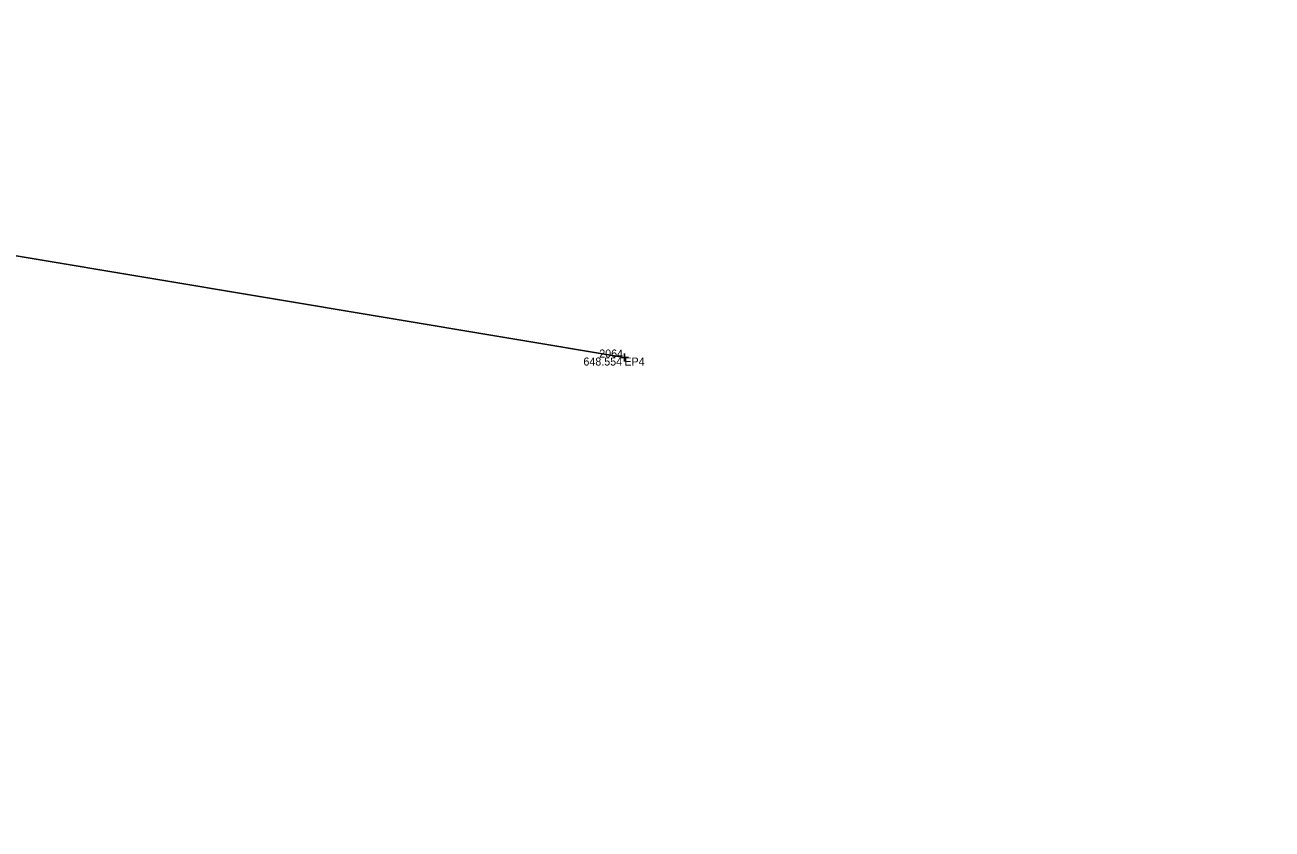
# Model space of a CAD drawing. Extents: x 2197382 to 2204062, y 634117 to 636522.
# Drawn here: x 2202771.2 to 2202927, y 635131.4 to 635231.8 of the extents above; entities that cross this region are included whole.
import ezdxf

# ---------------------------------------------------------------- set-up
doc = ezdxf.new("R2010")
doc.units = 0
for name, color, linetype in [('_CIVIL_CONSTRUCTION', 7, 'Continuous'), ('BR_X_SV_Deck_Top', 7, 'Continuous'), ('GE_P_Alignment_100_Distances', 7, 'Continuous'), ('SH_Border', 7, 'Continuous'), ('SH_Cut_Line', 7, 'Continuous'), ('SH_Data', 7, 'Continuous')]:
    doc.layers.add(name, color=color, linetype=linetype)

msp = doc.modelspace()

# ---------------------------------------------------------------- linework, layer by layer
at = {"layer": '_CIVIL_CONSTRUCTION'}
for p, q in [((2202845.58, 635190.3), (2202846.58, 635190.3)), ((2202846.08, 635190.8), (2202846.08, 635189.8)), ((2202846.08, 635190.3), (2202846.08, 635190.3))]:
    msp.add_line(p, q, dxfattribs=at)
at = {"layer": 'BR_X_SV_Deck_Top'}
for points in [[(2202458.05, 635216.68), (2202477.12, 635219.98), (2202511.72, 635243.78), (2202554.96, 635262.3), (2202588.01, 635280.67), (2202608.34, 635292.39), (2202640.83, 635312.14), (2202668.15, 635329.95), (2202698.57, 635351.31), (2202722.13, 635368.65), (2202754.6, 635393.43), (2202777.49, 635412.29), (2202789.61, 635422.64)], [(2202895.36, 635391.81), (2202885.35, 635387.33), (2202865.19, 635377.21), (2202839.04, 635363.76), (2202813.1, 635349.72), (2202789.18, 635336.14), (2202762.39, 635320.29), (2202740.67, 635306.56), (2202716.63, 635290.83), (2202693.39, 635275.34), (2202664.57, 635254.79), (2202633.54, 635231.77), (2202595.89, 635201.64), (2202569.4, 635178.62), (2202555.17, 635165.67)], [(2202923.18, 635376.2), (2202906.17, 635369.08), (2202881.49, 635355.93), (2202846.74, 635338.13), (2202819.01, 635322.65), (2202790.14, 635306.09), (2202754.02, 635283.78), (2202709.42, 635255.58), (2202663.28, 635220.88), (2202620.57, 635187.91), (2202595.28, 635167.4), (2202582.51, 635156.81)]]:
    msp.add_open_spline(points, degree=3, dxfattribs=at)
at = {"layer": 'GE_P_Alignment_100_Distances'}
msp.add_lwpolyline([(2202482.63, 635259.7), (2202569.32, 635240.74), (2202617.18, 635230.71), (2202631.86, 635227.59), (2202654.83, 635223.14), (2202694.02, 635215.69), (2202726.45, 635210.27), (2202846.08, 635190.3)], dxfattribs=at)
for points in [[(2202926.99, 635398.22), (2202911.05, 635391.27), (2202884.78, 635379.22), (2202850.25, 635362.17), (2202828.22, 635350.04), (2202808.09, 635339.2), (2202790.85, 635329.04), (2202764, 635313.32), (2202738.78, 635297.64), (2202713.05, 635280.58), (2202697.02, 635269.6), (2202684.53, 635260.86), (2202668.99, 635249.75), (2202642.65, 635230.81), (2202596.56, 635193.89), (2202560.68, 635163.16), (2202538.31, 635142.81)], [(2202919.5, 635378.37), (2202901.45, 635370.68), (2202875.94, 635356.88), (2202844.59, 635341.6), (2202825.86, 635330.82), (2202809.47, 635322.02), (2202780.05, 635304.41), (2202746.06, 635283), (2202707.72, 635258.18), (2202682.24, 635240.21), (2202658.95, 635222.26), (2202614.14, 635189.25), (2202577.35, 635157.52), (2202549.51, 635131.43)]]:
    msp.add_open_spline(points, degree=3, dxfattribs=at)

# ---------------------------------------------------------------- texts
at = {"layer": 'SH_Border'}
msp.add_text('EP4', height=1, dxfattribs=at).set_placement((2202846.08, 635189.3))
at = {"layer": 'SH_Cut_Line'}
msp.add_text('2064', height=1, dxfattribs=at).set_placement((2202842.94, 635190.3))
at = {"layer": 'SH_Data'}
msp.add_text('648.554', height=1, dxfattribs=at).set_placement((2202840.96, 635189.3))

doc.saveas('drawing.dxf')
